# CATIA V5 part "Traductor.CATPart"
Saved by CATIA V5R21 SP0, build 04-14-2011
Part number: Traductor
Bounding box of the stored display mesh (mm): x -20 to 20, y -20 to 20, z 5.75 to 60
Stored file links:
  C:\Users\MIRCEA\Desktop\PRRO\CATIAV5\Traductor.CATPart
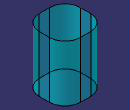
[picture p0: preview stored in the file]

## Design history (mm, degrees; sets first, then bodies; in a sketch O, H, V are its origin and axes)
Body1 (main body)
  Plane1: type Offset, RefPlane xy-plane, Offset 5.75
  Sketch1 on Plane1, origin (0, 0, 5.75), H (1, 0, 0), V (0, 1, 0)
    line L1 (20, 20) -> (20, -20)
    line L2 (20, -20) -> (-20, -20)
    line L3 (-20, -20) -> (-20, 20)
    line L4 (-20, 20) -> (20, 20)
    point P1 (20, 20)
    distance P1 V = 20
    distance P1 H = 20
    vertical: L1 V, L3 V
    horizontal: L2 H, L4 H
    equidistance: L1 L3 O, L2 L4 O
  Pad1: profile Sketch1, direction (0, 0, 1), length 54.25
  Fillet1: radius 15, on edge [face of Pad1 from Sketch1.L3 | face of Pad1 from Sketch1.L4]; edge [face of Pad1 from Sketch1.L4 | face of Pad1 from Sketch1.L1]; edge [face of Pad1 from Sketch1.L2 | face of Pad1 from Sketch1.L3]; edge [face of Pad1 from Sketch1.L1 | face of Pad1 from Sketch1.L2]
